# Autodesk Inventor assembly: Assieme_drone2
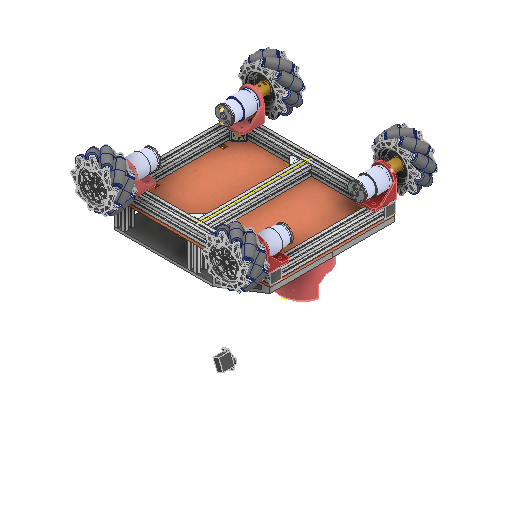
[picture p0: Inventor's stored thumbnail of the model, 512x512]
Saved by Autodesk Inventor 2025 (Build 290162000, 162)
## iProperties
Created: 2025-05
Part Number: Assieme_drone2
Document SubType Name: Assembly
Designer: R5800u
Author: R5800u
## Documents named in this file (34)
- C:\Users\R5800u\Desktop\drone_v3\Workgroups\NotInProject\Assieme_drone2.iam
- C:\Users\R5800u\Desktop\drone_v3\Workgroups\NotInProject\tslot-20x20-1.ipt
- C:\Users\R5800u\Desktop\drone_v3\Workgroups\NotInProject\tslot-20x20-1_MIR.ipt
- C:\Users\R5800u\Desktop\drone_v3\Workgroups\NotInProject\tslot-20x20-2.ipt
- C:\Users\R5800u\Desktop\drone_v3\Workgroups\NotInProject\SNSD20x20.ipt
- C:\Users\R5800u\Desktop\drone_v3\Workgroups\NotInProject\SNSD20x20_MIR.ipt
- C:\Users\R5800u\Desktop\drone_v3\Workgroups\NotInProject\tslot-20x20-3.ipt
- C:\Users\R5800u\Desktop\drone_v3\Workgroups\NotInProject\MM-JGB37 v4.ipt
- C:\Users\R5800u\Desktop\drone_v3\Workgroups\NotInProject\JGB37-520.ipt
- C:\Users\R5800u\Documents\Inventor\Content Center Files\R2025\it-IT\AS 1427(05)\AS 1427 - M4 x 10(5) II.ipt
- C:\Users\R5800u\Desktop\drone_v3\Workgroups\NotInProject\MM-JGB37 v4_MIR.ipt
- C:\Users\R5800u\Desktop\drone_v3\Workgroups\NotInProject\JGB37-520_MIR.ipt
- C:\Users\R5800u\Desktop\drone_v3\Workgroups\NotInProject\MM-JGB37 v4_MIR1.ipt
- C:\Users\R5800u\Desktop\drone_v3\Workgroups\NotInProject\JGB37-520_MIR1.ipt
- C:\Users\R5800u\Desktop\drone_v3\Workgroups\NotInProject\MM-JGB37 v4_MIR_MIR.ipt
- C:\Users\R5800u\Desktop\drone_v3\Workgroups\NotInProject\JGB37-520_MIR_MIR.ipt
- C:\Users\R5800u\Desktop\drone_v3\Workgroups\NotInProject\Mecanum wheel - right.ipt
- C:\Users\R5800u\Desktop\drone_v3\Workgroups\NotInProject\Mecanum wheel - left.ipt
- C:\Users\R5800u\Desktop\drone_v3\Workgroups\NotInProject\albero_ottonre_12x6.ipt
- C:\Users\R5800u\Desktop\drone_v3\Workgroups\NotInProject\tappi_tslot.ipt
- C:\Users\R5800u\Desktop\drone_v3\Workgroups\NotInProject\pianoA.ipt
- C:\Users\R5800u\Desktop\drone_v3\Workgroups\NotInProject\batteira_6V_LIFEPO4.ipt
- C:\Users\R5800u\Desktop\drone_v3\Workgroups\NotInProject\L298N.ipt
- C:\Users\R5800u\Desktop\drone_v3\Workgroups\NotInProject\ESP32-C3 Super Mini breakout expansion board module -Assembly.iam
- C:\Users\R5800u\Desktop\drone_v3\Workgroups\NotInProject\beetle ESP32-C3.iam
- C:\Users\R5800u\Desktop\drone_v3\Workgroups\NotInProject\piano2.ipt
- C:\Users\R5800u\Desktop\drone_v3\Workgroups\NotInProject\Servo_20kg.ipt
- C:\Users\R5800u\Desktop\drone_v3\Workgroups\NotInProject\base_servo1.ipt
- C:\Users\R5800u\Desktop\drone_v3\Workgroups\NotInProject\disco.mg995.Al.ipt
- C:\Users\R5800u\Desktop\drone_v3\Workgroups\NotInProject\leva1.ipt
- C:\Users\R5800u\Desktop\drone_v3\Workgroups\NotInProject\leva2.ipt
- C:\Users\R5800u\Desktop\drone_v3\Workgroups\NotInProject\MG90s.ipt
- C:\Users\R5800u\Desktop\drone_v3\Workgroups\NotInProject\lato.ipt
- C:\Users\R5800u\Desktop\drone_v3\Workgroups\NotInProject\lato_MIR2.ipt
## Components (56 placed, 33 different names)
1. tslot-20x20-1:1
2. tslot-20x20-1_MIR:1
3. tslot-20x20-2:1 — Allineato:10, Coincidente:17, Coincidente:21, Coincidente:26, Allineato:30, Simmetria:3, Coincidente:58, Coincidente:59, Allineato:55, Allineato:58
4. tslot-20x20-2:2
5. SNSD20x20:1 — Allineato:14, Coincidente:22, Coincidente:23
6. SNSD20x20:2 — Allineato:13, Coincidente:20, Coincidente:21
7. SNSD20x20_MIR:1 — Allineato:15, Coincidente:24, Coincidente:27
8. SNSD20x20_MIR:2 — Allineato:16, Coincidente:25, Coincidente:26
9. tslot-20x20-2:3 — Allineato:17, Coincidente:28, Allineato:30, Allineato:32, Coincidente:30, Allineato:33, Coincidente:31
10. SNSD20x20_MIR:3 — Allineato:32, Coincidente:29, Coincidente:30
11. SNSD20x20:3 — Allineato:33, Coincidente:31, Coincidente:32
12. tslot-20x20-3:7 — Coincidente:70, Allineato:59, Allineato:62
13. MM-JGB37 v4:1
14. JGB37-520:1 — Rotazionale:1, Coincidente:43, Coincidente:44, Rigido:5
15. AS 1427 H - Metrico M4 x 10:1 — Coincidente:47
16. AS 1427 H - Metrico M4 x 10:2 — Coincidente:49
17. AS 1427 H - Metrico M4 x 10:3 — Rotazionale:2
18. MM-JGB37 v4_MIR:1 — Coincidente:50, Coincidente:51, Rotazionale:3, Coincidente:67, Allineato:53, Allineato:54
19. JGB37-520_MIR:1 — Coincidente:50, Coincidente:51, Rotazionale:3, Rigido:6
20. MM-JGB37 v4_MIR1:1 — Coincidente:52, Coincidente:53, Rotazionale:4, Coincidente:58, Coincidente:59, Allineato:48
21. JGB37-520_MIR1:1 — Coincidente:52, Coincidente:53, Rotazionale:4, Rigido:1
22. MM-JGB37 v4_MIR_MIR:1 — Coincidente:54, Coincidente:55, Rotazionale:5, Coincidente:68, Allineato:55, Allineato:56
23. JGB37-520_MIR_MIR:1 — Coincidente:54, Coincidente:55, Rotazionale:5, Rigido:7
24. Mecanum wheel - right:1 — Coincidente:60, Coincidente:64
25. Mecanum wheel - right:2 — Coincidente:62, Coincidente:63
26. Mecanum wheel - left:1 — Coincidente:56, Angolo:1, Coincidente:57
27. Mecanum wheel - left:2 — Coincidente:61, Coincidente:65
28. albero_ottonre_12x6:1 — Coincidente:56, Angolo:1, Coincidente:57, Rigido:1
29. albero_ottonre_12x6:2 — Coincidente:61, Coincidente:65, Rigido:5
30. albero_ottonre_12x6:3 — Coincidente:60, Coincidente:64, Rigido:6
31. albero_ottonre_12x6:4 — Coincidente:62, Coincidente:63, Rigido:7
32. tappi_tslot:1 — Allineato:51
33. tappi_tslot:2 — Rotazionale:6
34. pianoA:1 — Coincidente:69, Allineato:57, Allineato:58, Coincidente:70, Allineato:59, Allineato:60, Coincidente:71, Allineato:63, Coincidente:73, Rotazionale:7, Allineato:65, Coincidente:77, Allineato:83, Coincidente:78, Coincidente:79, Allineato:84, Allineato:85, Rotazionale:12, Rotazionale:13, Allineato:93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
35. batteira_6V_LIFEPO4:1 — Coincidente:71, Allineato:63, Coincidente:72, Allineato:64
36. batteira_6V_LIFEPO4:2 — Coincidente:72, Allineato:64, Coincidente:73, Allineato:83, Coincidente:80
37. tslot-20x20-3:8 — Rotazionale:7, Allineato:65, Allineato:88
38. L298N:2 — Coincidente:79, Allineato:85, Allineato:86
39. L298N:3 — Coincidente:78, Allineato:84, Allineato:86, Allineato:87, Coincidente:80
40. ESP32-C3 Super Mini breakout expansion board module -Assembly:1 [sub-assembly] — Coincidente:77, Allineato:87
41. beetle ESP32-C3:1 [sub-assembly]
42. tslot-20x20-3:13 — Rotazionale:12, Allineato:93
43. tslot-20x20-3:14 — Rotazionale:13, Allineato:94
44. piano2:1 — Allineato:88, Angolo:2, Allineato:99
45. tappi_tslot:3 — Rigido:8
46. tappi_tslot:4 — Coincidente:82, Coincidente:83, Allineato:92
47. base_servo1:1 — Coincidente:84, Coincidente:85, Coincidente:86, Coincidente:87, Allineato:95
48. disco.mg995.Al:1 — Rotazionale:14, Rotazionale:15
49. Servo_20kg:1 — Coincidente:86, Coincidente:87, Allineato:95, Rotazionale:14
50. leva1:1 — Rotazionale:15, Allineato:96, Coincidente:88, Coincidente:89, Angolo:2
51. Servo_20kg:2 — Rotazionale:16, Allineato:96, Coincidente:88, Coincidente:89
52. disco.mg995.Al:2 — Rotazionale:16, Rotazionale:17
53. leva2:2 — Rotazionale:17, Rotazionale:18, Angolo:3
54. MG90s:1 — Rotazionale:18, Angolo:3
55. lato:1 — Coincidente:90, Allineato:97, Allineato:98, Allineato:99
56. lato_MIR2:1
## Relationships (114: Mate 54, Flush 37, RevoluteJoint 14, WeldJoint 5, Angle 3, Symmetry 1)
- Allineato:10 [Flush]: tslot-20x20-2:1
- Coincidente:17 [Mate]: tslot-20x20-2:1
- Allineato:13 [Flush]: SNSD20x20:2
- Coincidente:20 [Mate]: SNSD20x20:2
- Coincidente:21 [Mate]: tslot-20x20-2:1 ↔ SNSD20x20:2
- Allineato:14 [Flush]: SNSD20x20:1
- Coincidente:22 [Mate]: SNSD20x20:1
- Coincidente:23 [Mate]: SNSD20x20:1
- Allineato:15 [Flush]: SNSD20x20_MIR:1
- Allineato:16 [Flush]: SNSD20x20_MIR:2
- Coincidente:24 [Mate]: SNSD20x20_MIR:1
- Coincidente:25 [Mate]: SNSD20x20_MIR:2
- Coincidente:26 [Mate]: tslot-20x20-2:1 ↔ SNSD20x20_MIR:2
- Coincidente:27 [Mate]: SNSD20x20_MIR:1
- Allineato:17 [Flush]: tslot-20x20-2:3
- Coincidente:28 [Mate]: tslot-20x20-2:3
- Allineato:30 [Flush]: tslot-20x20-2:1 ↔ tslot-20x20-2:3
- Allineato:32 [Flush]: tslot-20x20-2:3 ↔ SNSD20x20_MIR:3
- Coincidente:29 [Mate]: SNSD20x20_MIR:3
- Coincidente:30 [Mate]: tslot-20x20-2:3 ↔ SNSD20x20_MIR:3
- Allineato:33 [Flush]: tslot-20x20-2:3 ↔ SNSD20x20:3
- Coincidente:31 [Mate]: tslot-20x20-2:3 ↔ SNSD20x20:3
- Coincidente:32 [Mate]: SNSD20x20:3
- Simmetria:3 [Symmetry]: tslot-20x20-2:1
- Rotazionale:1 [RevoluteJoint]: JGB37-520:1
- Coincidente:43 [Mate]: JGB37-520:1
- Coincidente:44 [Mate]: JGB37-520:1
- Coincidente:47 [Mate]: AS 1427 H - Metrico M4 x 10:1
- Coincidente:49 [Mate]: AS 1427 H - Metrico M4 x 10:2
- Rotazionale:2 [RevoluteJoint]: AS 1427 H - Metrico M4 x 10:3
- Coincidente:50 [Mate]: MM-JGB37 v4_MIR:1 ↔ JGB37-520_MIR:1
- Coincidente:51 [Mate]: MM-JGB37 v4_MIR:1 ↔ JGB37-520_MIR:1
- Rotazionale:3 [RevoluteJoint]: MM-JGB37 v4_MIR:1 ↔ JGB37-520_MIR:1
- Coincidente:52 [Mate]: MM-JGB37 v4_MIR1:1 ↔ JGB37-520_MIR1:1
- Coincidente:53 [Mate]: MM-JGB37 v4_MIR1:1 ↔ JGB37-520_MIR1:1
- Coincidente:54 [Mate]: MM-JGB37 v4_MIR_MIR:1 ↔ JGB37-520_MIR_MIR:1
- Coincidente:55 [Mate]: MM-JGB37 v4_MIR_MIR:1 ↔ JGB37-520_MIR_MIR:1
- Rotazionale:4 [RevoluteJoint]: MM-JGB37 v4_MIR1:1 ↔ JGB37-520_MIR1:1
- Rotazionale:5 [RevoluteJoint]: MM-JGB37 v4_MIR_MIR:1 ↔ JGB37-520_MIR_MIR:1
- Coincidente:56 [Mate]: Mecanum wheel - left:1 ↔ albero_ottonre_12x6:1
- Angolo:1 [Angle]: Mecanum wheel - left:1 ↔ albero_ottonre_12x6:1
- Coincidente:57 [Mate]: Mecanum wheel - left:1 ↔ albero_ottonre_12x6:1
- Coincidente:58 [Mate]: tslot-20x20-2:1 ↔ MM-JGB37 v4_MIR1:1
- Coincidente:59 [Mate]: tslot-20x20-2:1 ↔ MM-JGB37 v4_MIR1:1
- Allineato:48 [Flush]: MM-JGB37 v4_MIR1:1
- Rigido:1 [WeldJoint]: JGB37-520_MIR1:1 ↔ albero_ottonre_12x6:1
- Coincidente:60 [Mate]: Mecanum wheel - right:1 ↔ albero_ottonre_12x6:3
- Coincidente:61 [Mate]: Mecanum wheel - left:2 ↔ albero_ottonre_12x6:2
- Coincidente:62 [Mate]: Mecanum wheel - right:2 ↔ albero_ottonre_12x6:4
- Coincidente:63 [Mate]: Mecanum wheel - right:2 ↔ albero_ottonre_12x6:4
- Coincidente:64 [Mate]: Mecanum wheel - right:1 ↔ albero_ottonre_12x6:3
- Coincidente:65 [Mate]: Mecanum wheel - left:2 ↔ albero_ottonre_12x6:2
- Allineato:51 [Flush]: tappi_tslot:1
- Rotazionale:6 [RevoluteJoint]: tappi_tslot:2
- Rigido:5 [WeldJoint]: JGB37-520:1 ↔ albero_ottonre_12x6:2
- Coincidente:67 [Mate]: MM-JGB37 v4_MIR:1
- Allineato:53 [Flush]: MM-JGB37 v4_MIR:1
- Allineato:54 [Flush]: MM-JGB37 v4_MIR:1
- Rigido:6 [WeldJoint]: JGB37-520_MIR:1 ↔ albero_ottonre_12x6:3
- Coincidente:68 [Mate]: MM-JGB37 v4_MIR_MIR:1
- Allineato:55 [Flush]: tslot-20x20-2:1 ↔ MM-JGB37 v4_MIR_MIR:1
- Allineato:56 [Flush]: MM-JGB37 v4_MIR_MIR:1
- Rigido:7 [WeldJoint]: JGB37-520_MIR_MIR:1 ↔ albero_ottonre_12x6:4
- Coincidente:69 [Mate]: pianoA:1
- Allineato:57 [Flush]: pianoA:1
- Allineato:58 [Flush]: tslot-20x20-2:1 ↔ pianoA:1
- Coincidente:70 [Mate]: tslot-20x20-3:7 ↔ pianoA:1
- Allineato:59 [Flush]: tslot-20x20-3:7 ↔ pianoA:1
- Allineato:60 [Flush]: pianoA:1
- Allineato:62 [Flush]: tslot-20x20-3:7
- Coincidente:71 [Mate]: pianoA:1 ↔ batteira_6V_LIFEPO4:1
- Allineato:63 [Flush]: pianoA:1 ↔ batteira_6V_LIFEPO4:1
- Coincidente:72 [Mate]: batteira_6V_LIFEPO4:1 ↔ batteira_6V_LIFEPO4:2
- Allineato:64 [Flush]: batteira_6V_LIFEPO4:1 ↔ batteira_6V_LIFEPO4:2
- Coincidente:73 [Mate]: pianoA:1 ↔ batteira_6V_LIFEPO4:2
- Rotazionale:7 [RevoluteJoint]: pianoA:1 ↔ tslot-20x20-3:8
- Allineato:65 [Flush]: pianoA:1 ↔ tslot-20x20-3:8
- Coincidente:77 [Mate]: pianoA:1 ↔ ESP32-C3 Super Mini breakout expansion board module -Assembly:1
- Allineato:83 [Flush]: pianoA:1 ↔ batteira_6V_LIFEPO4:2
- Coincidente:78 [Mate]: pianoA:1 ↔ L298N:3
- Coincidente:79 [Mate]: pianoA:1 ↔ L298N:2
- Allineato:84 [Flush]: pianoA:1 ↔ L298N:3
- Allineato:85 [Flush]: pianoA:1 ↔ L298N:2
- Allineato:86 [Flush]: L298N:2 ↔ L298N:3
- Allineato:87 [Flush]: L298N:3 ↔ ESP32-C3 Super Mini breakout expansion board module -Assembly:1
- Coincidente:80 [Mate]: batteira_6V_LIFEPO4:2 ↔ L298N:3
- Rotazionale:12 [RevoluteJoint]: pianoA:1 ↔ tslot-20x20-3:13
- Rotazionale:13 [RevoluteJoint]: pianoA:1 ↔ tslot-20x20-3:14
- Allineato:88 [Flush]: tslot-20x20-3:8 ↔ piano2:1
- Coincidente:82 [Mate]: tappi_tslot:4
- Coincidente:83 [Mate]: tappi_tslot:4
- Allineato:92 [Flush]: tappi_tslot:4
- Rigido:8 [WeldJoint]: tappi_tslot:3
- Allineato:93 [Flush]: pianoA:1 ↔ tslot-20x20-3:13
- Allineato:94 [Flush]: pianoA:1 ↔ tslot-20x20-3:14
- Coincidente:84 [Mate]: pianoA:1 ↔ base_servo1:1
- Coincidente:85 [Mate]: base_servo1:1
- Coincidente:86 [Mate]: base_servo1:1 ↔ Servo_20kg:1
- Coincidente:87 [Mate]: base_servo1:1 ↔ Servo_20kg:1
- Allineato:95 [Flush]: base_servo1:1 ↔ Servo_20kg:1
- Rotazionale:14 [RevoluteJoint]: disco.mg995.Al:1 ↔ Servo_20kg:1
- Rotazionale:15 [RevoluteJoint]: disco.mg995.Al:1 ↔ leva1:1
- Rotazionale:16 [RevoluteJoint]: Servo_20kg:2 ↔ disco.mg995.Al:2
- Allineato:96 [Flush]: leva1:1 ↔ Servo_20kg:2
- Coincidente:88 [Mate]: leva1:1 ↔ Servo_20kg:2
- Coincidente:89 [Mate]: leva1:1 ↔ Servo_20kg:2
- Angolo:2 [Angle]: piano2:1 ↔ leva1:1
- Rotazionale:17 [RevoluteJoint]: disco.mg995.Al:2 ↔ leva2:2
- Rotazionale:18 [RevoluteJoint]: leva2:2 ↔ MG90s:1
- Angolo:3 [Angle]: leva2:2 ↔ MG90s:1
- Coincidente:90 [Mate]: pianoA:1 ↔ lato:1
- Allineato:97 [Flush]: pianoA:1 ↔ lato:1
- Allineato:98 [Flush]: pianoA:1 ↔ lato:1
- Allineato:99 [Flush]: piano2:1 ↔ lato:1
